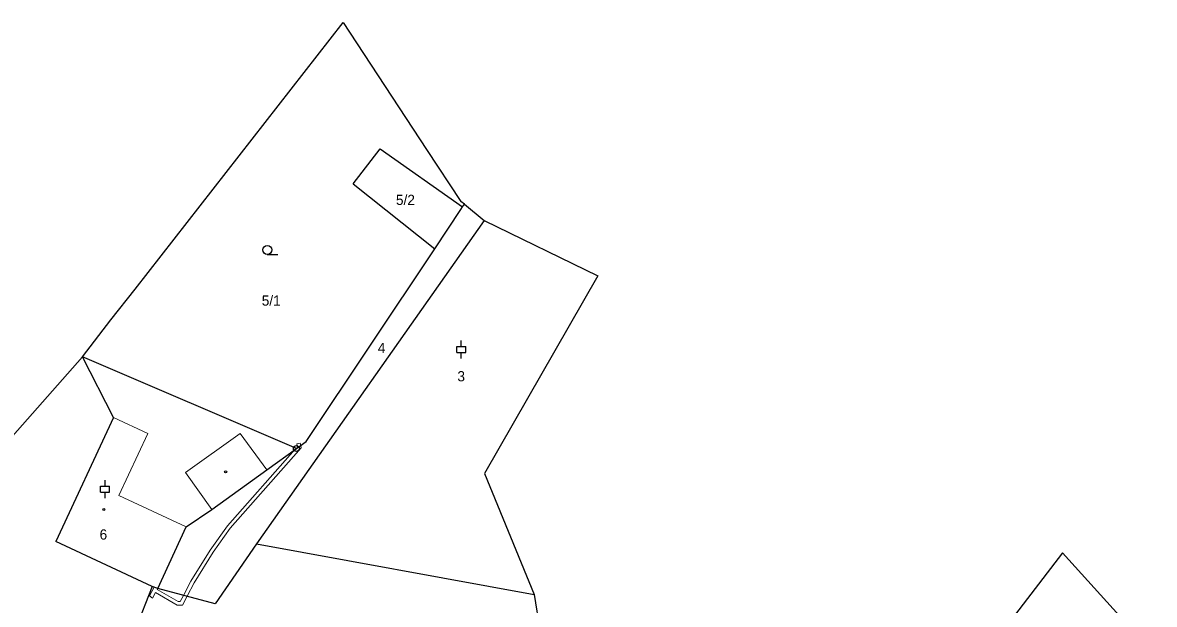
# Model space of a CAD drawing. Extents: x -727701 to -724405, y -960481 to -957284.
# Drawn here: x -726807.6 to -726618.9, y -958022 to -957925 of the extents above; entities that cross this region are included whole.
import ezdxf
from ezdxf.enums import TextEntityAlignment as Align

# ---------------------------------------------------------------- set-up
doc = ezdxf.new("R2010")
doc.units = 0
doc.header["$LTSCALE"] = 0.68
for name, color, linetype, lineweight in [('1', 7, 'Continuous', 25), ('13', 7, 'Continuous', 13), ('3', 7, 'Continuous', 25), ('4', 7, 'Continuous', 13), ('5', 7, 'Continuous', 25), ('8', 7, 'Continuous', 25)]:
    doc.layers.add(name, color=color, linetype=linetype, lineweight=lineweight)
doc.layers.add('2', color=7, linetype='Continuous')

msp = doc.modelspace()

# ---------------------------------------------------------------- linework, layer by layer
at = {"layer": '1'}
for p, q in [((-726788.82, -957969.45), (-726754.14, -957925.01)), ((-726754.14, -957925.01), (-726740.23, -957946.13)), ((-726752.49, -957951.88), (-726748, -957946.06)), ((-726748, -957946.06), (-726734.23, -957955.73)), ((-726740.23, -957946.13), (-726734.51, -957954.82)), ((-726752.49, -957951.88), (-726738.87, -957962.69)), ((-726733.93, -957955.29), (-726734.51, -957954.82)), ((-726734.23, -957955.73), (-726733.93, -957955.29)), ((-726733.93, -957955.29), (-726730.63, -957957.99)), ((-726738.87, -957962.69), (-726734.51, -957956.16)), ((-726734.51, -957956.16), (-726734.23, -957955.73)), ((-726730.63, -957957.99), (-726768.61, -958011.89)), ((-726730.63, -957957.99), (-726711.68, -957967.18)), ((-726760.32, -957994.82), (-726738.87, -957962.69)), ((-726711.68, -957967.18), (-726730.58, -958000.15)), ((-726792.9, -957974.55), (-726788.82, -957969.45)), ((-726797.61, -957980.7), (-726792.9, -957974.55)), ((-726797.61, -957980.7), (-726814.9, -958000.25)), ((-726761.94, -957995.98), (-726797.61, -957980.7)), ((-726792.47, -957990.81), (-726797.61, -957980.7)), ((-726792.47, -957990.81), (-726802.04, -958011.49)), ((-726761.94, -957995.98), (-726760.32, -957994.82)), ((-726766.9, -957999.55), (-726761.94, -957995.98)), ((-726776.05, -958006.15), (-726766.9, -957999.55)), ((-726730.58, -958000.15), (-726722.3, -958020.3)), ((-726780.31, -958009.05), (-726776.05, -958006.15)), ((-726785.07, -958019.34), (-726780.31, -958009.05)), ((-726786, -958019), (-726802.04, -958011.49)), ((-726768.61, -958011.89), (-726775.47, -958021.85)), ((-726768.61, -958011.89), (-726722.3, -958020.3)), ((-726634.18, -958013.37), (-726656.63, -958042.62)), ((-726634.18, -958013.37), (-726618.86, -958030.28)), ((-726786, -958019), (-726791.84, -958033.67)), ((-726785.07, -958019.34), (-726786, -958019)), ((-726775.47, -958021.85), (-726785.07, -958019.34)), ((-726722.3, -958020.3), (-726719.49, -958037.65))]:
    msp.add_line(p, q, dxfattribs=at)
at = {"layer": '13'}
for points in [[(-726761.75, -957995.84), (-726761.22, -957995.46), (-726761.3, -957995.07), (-726761.89, -957995.2)], [(-726780.77, -958020.46), (-726780.17, -958020.62), (-726779.01, -958018.4), (-726775.85, -958013.25), (-726773, -958009.26), (-726761.12, -957995.89), (-726761.22, -957995.46), (-726761.75, -957995.84), (-726761.94, -957995.98), (-726762.14, -957996.12), (-726773.46, -958008.88), (-726776.35, -958012.91), (-726779.53, -958018.1)], [(-726785.68, -958019.12), (-726786.46, -958020.56), (-726785.95, -958020.93), (-726785.44, -958020.01), (-726781.83, -958022.08), (-726780.94, -958022.08), (-726780.17, -958020.62), (-726780.77, -958020.46), (-726781.3, -958021.48), (-726781.67, -958021.48), (-726785.15, -958019.49), (-726785.07, -958019.34)]]:
    msp.add_lwpolyline(points, close=True, dxfattribs=at)
at = {"layer": '3'}
for p, q in [((-726766.803, -957963.63), (-726765.053, -957963.63)), ((-726734.45, -957978.991), (-726734.45, -957977.99)), ((-726735.201, -957978.991), (-726733.699, -957978.991)), ((-726735.201, -957979.992), (-726735.201, -957978.991)), ((-726735.201, -957979.992), (-726733.699, -957979.992)), ((-726734.45, -957980.99), (-726734.45, -957979.992)), ((-726733.699, -957979.992), (-726733.699, -957978.991)), ((-726794.591, -958002.271), (-726793.089, -958002.271)), ((-726794.591, -958003.272), (-726794.591, -958002.271)), ((-726793.84, -958002.271), (-726793.84, -958001.27)), ((-726793.089, -958003.272), (-726793.089, -958002.271)), ((-726794.591, -958003.272), (-726793.089, -958003.272)), ((-726793.84, -958004.27), (-726793.84, -958003.272))]:
    msp.add_line(p, q, dxfattribs=at)
msp.add_circle((-726766.8029, -957962.8798), 0.75, dxfattribs=at)
at = {"layer": '4'}
for p, q in [((-726792.47, -957990.81), (-726786.72, -957993.47)), ((-726786.72, -957993.47), (-726791.56, -958003.84)), ((-726780.45, -958000), (-726771.3, -957993.5)), ((-726771.3, -957993.5), (-726766.9, -957999.55)), ((-726776.05, -958006.15), (-726780.45, -958000)), ((-726791.56, -958003.84), (-726780.31, -958009.05))]:
    msp.add_line(p, q, dxfattribs=at)
at = {"layer": '5'}
for centre in [(-726773.7468, -957999.8592), (-726794.0468, -958006.1492)]:
    msp.add_circle(centre, 0.175, dxfattribs=at)
at = {"layer": '8'}
for radius in [0.5, 0.0303]:
    msp.add_circle((-726761.94, -957995.9799), radius, dxfattribs=at)

# ---------------------------------------------------------------- texts
at = {"layer": '2'}
msp.add_text('5/2', height=1.7, dxfattribs=at).set_placement((-726743.76, -957955.395), align=Align.CENTER)
for s, p in [('5/1', (-726767.72, -957972.175)), ('4', (-726748.37, -957980.075)), ('3', (-726735.09, -957984.795)), ('6', (-726794.76, -958011.165))]:
    msp.add_text(s, height=1.7, dxfattribs=at).set_placement(p)

doc.saveas('drawing.dxf')
